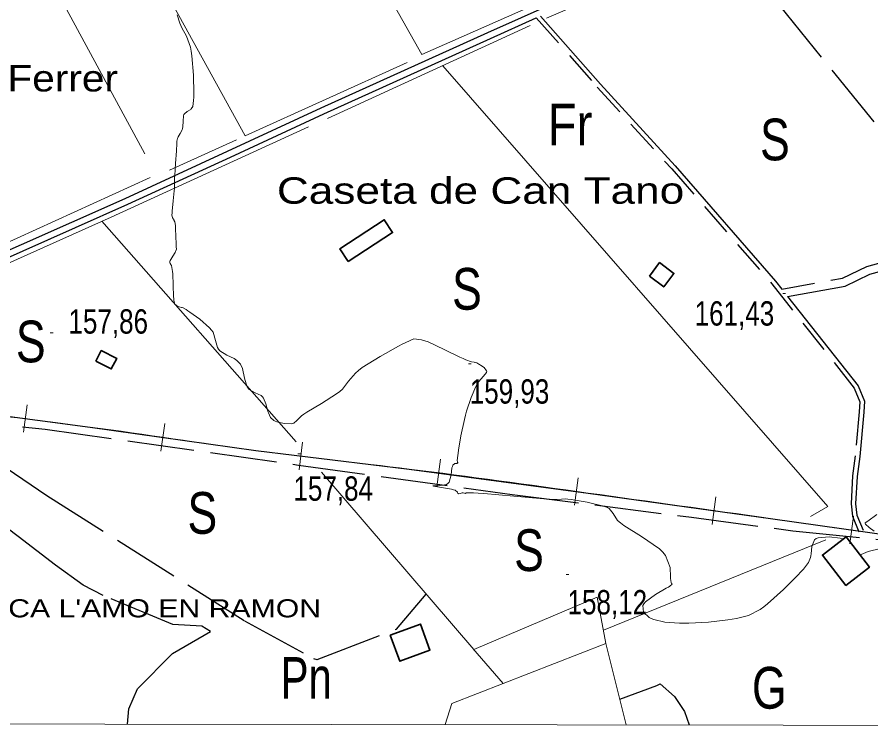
# Model space of a CAD drawing. Extents: x -807245 to 6129983, y -54972206 to 262146364.
# Drawn here: x 489594.4 to 489901.6, y 4381810.3 to 4382068.1 of the extents above; entities that cross this region are included whole.
import ezdxf
from ezdxf.enums import TextEntityAlignment as Align

# ---------------------------------------------------------------- set-up
doc = ezdxf.new("R2010")
doc.units = 0
doc.header["$LTSCALE"] = 4
doc.linetypes.add('LONG_DASHED', pattern=[7.5, 6, -1.5])
doc.linetypes.add('MEDIUM_DASHED', pattern=[4.5, 3, -1.5])
for name, color, linetype, lineweight in [('1', 7, 'Continuous', 13), ('25', 7, 'LONG_DASHED', 25), ('27', 7, 'Continuous', 25), ('38', 7, 'Continuous', 25), ('39', 7, 'Continuous', 13), ('47', 7, 'Continuous', 35), ('51', 7, 'Continuous', 13), ('7', 7, 'Continuous', 13), ('9', 7, 'Continuous', 13)]:
    doc.layers.add(name, color=color, linetype=linetype, lineweight=lineweight)
doc.layers.add('31', color=7, linetype='Continuous')
doc.layers.add('5', color=7, linetype='Continuous')

msp = doc.modelspace()

# ---------------------------------------------------------------- linework, layer by layer
at = {"layer": '1'}
msp.add_lwpolyline([(487678, 4384129), (491255.4, 4384123.8), (491252.6, 4381811.5), (487674.1, 4381816.7)], close=True, dxfattribs=at)
at = {"layer": '25'}
msp.add_line((489849.71, 4382095.68), (489987.15, 4381926.15), dxfattribs=at)
for points in [[(489452.44, 4381947.99), (489470.81, 4381945.01), (489504.4, 4381935.18), (489529.88, 4381929.13), (489553.54, 4381927.48), (489566.45, 4381923.64), (489604.56, 4381919.97), (489695.66, 4381907.04), (489772.54, 4381896.5), (489837.07, 4381888.24), (489873.55, 4381883.42), (489910.23, 4381879.72), (489957.75, 4381870.56), (490032.95, 4381858.19), (490087.19, 4381850.38), (490148.03, 4381842.93), (490197.43, 4381837.42), (490224.83, 4381836.07), (490255.25, 4381830.66), (490293.96, 4381826.86), (490348.9, 4381821.39)], [(489562.89, 4381924.71), (489605.15, 4381896.06), (489676.26, 4381851.04), (489701.09, 4381837.41), (489702.29, 4381837.14), (489702.37, 4381837.14), (489730.93, 4381848.04), (489741.63, 4381860.58)], [(489634.15, 4381813.85), (489634.66, 4381819.38), (489637.73, 4381826.5), (489650.35, 4381839.23), (489664.05, 4381847.18), (489660.86, 4381849.06), (489650.49, 4381849.73), (489625.44, 4381860.13), (489618.16, 4381863.87), (489608.25, 4381871), (489594.75, 4381881.28), (489586.21, 4381887.77), (489577.73, 4381895.08), (489567.94, 4381903.57), (489558.12, 4381913.63), (489556.12, 4381915.83), (489553.84, 4381913.16)], [(489811.23, 4381822.88), (489824.6, 4381827.75), (489825.78, 4381828.37), (489830.91, 4381823.83), (489834.55, 4381818.44), (489836.17, 4381813.56)]]:
    msp.add_lwpolyline(points, dxfattribs=at)
at = {"layer": '27'}
msp.add_spline([(491255.21, 4383970.03), (491244.34, 4383967.52), (491230.36, 4383957.66), (491230.81, 4383957.81), (491230.81, 4383957.81), (491220.15, 4383951.47), (491212.7, 4383943.01), (491205.06, 4383944.23), (491184.85, 4383957.71), (491152.82, 4383981.27), (491128.36, 4384004.58), (491128.29, 4384004.88), (491122.26, 4384021.39), (491095.75, 4384034.59), (491071.07, 4384059.32), (491064.71, 4384065.12)], degree=3, dxfattribs=at)
at = {"layer": '38'}
for points in [[(489532.56, 4381957.48), (489536.05, 4381958.89), (489576.74, 4381977.86), (489633.34, 4382002.95), (489670.16, 4382019.88), (489703.8, 4382035.47), (489763.73, 4382062.58), (489825.37, 4382090.18), (489886.58, 4382117.1), (489924.2, 4382133.95)], [(489150.21, 4381973.7), (489186.43, 4381969.89), (489217.49, 4381967.49), (489238.54, 4381965.85), (489269.93, 4381963.84), (489311.11, 4381960.54), (489355.93, 4381958), (489398.29, 4381954.28), (489439.39, 4381951.35), (489451.4, 4381951.23), (489463.3, 4381952.62), (489475.12, 4381953.31), (489487.87, 4381948.91), (489502.27, 4381945.57), (489507.66, 4381944.82), (489536.99, 4381956.73), (489577.71, 4381975.72), (489634.31, 4382000.8), (489671.15, 4382017.74), (489704.78, 4382033.33), (489764.7, 4382060.43), (489781.21, 4382067.82)], [(489782.76, 4382068.51), (489804.33, 4382044.05), (489831.15, 4382014.63), (489867.23, 4381973.2), (489869.5, 4381970.33)], [(489871.62, 4381967.65), (489892.31, 4381971.39), (489901.14, 4381975.63), (489912.92, 4381978.89), (489918.65, 4381980.97)], [(489871.62, 4381967.65), (489897.01, 4381935.53), (489899.3, 4381930.03), (489899.02, 4381926.05), (489897.56, 4381910.12), (489896.6, 4381902.97), (489896.06, 4381893.14), (489896.53, 4381889.02), (489898.75, 4381883.59)]]:
    msp.add_lwpolyline(points, dxfattribs=at)
at = {"layer": '38', "linetype": 'MEDIUM_DASHED'}
for points in [[(489781.21, 4382067.82), (489803.13, 4382042.97), (489829.95, 4382013.56), (489865.99, 4381972.17), (489895.61, 4381934.7), (489897.66, 4381929.76), (489897.41, 4381926.18), (489895.96, 4381910.3), (489894.99, 4381903.12), (489894.44, 4381893.09), (489894.95, 4381888.62), (489897.26, 4381882.98)], [(489869.5, 4381970.33), (489891.37, 4381974.29), (489900.07, 4381978.47), (489912, 4381981.77), (489917.62, 4381983.81)]]:
    msp.add_lwpolyline(points, dxfattribs=at)
at = {"layer": '39'}
for p, q in [((489596.7, 4381918.83), (489598.01, 4381928.74)), ((489646.19, 4381912.04), (489647.59, 4381921.94)), ((489695.84, 4381905.35), (489697.04, 4381915.27)), ((489745.39, 4381899.21), (489746.72, 4381909.12)), ((489794.95, 4381892.57), (489796.28, 4381902.48)), ((489844.45, 4381885.69), (489845.83, 4381895.59)), ((489893.96, 4381878.75), (489895.35, 4381888.65))]:
    msp.add_line(p, q, dxfattribs=at)
at = {"layer": '39', "lineweight": 25}
msp.add_lwpolyline([(489563.73, 4381928.23), (489620.66, 4381920.7), (489680.32, 4381912.26), (489735.44, 4381905.59), (489799.91, 4381896.95), (489865.43, 4381887.81), (489926.74, 4381879.18), (489976.6, 4381873.08), (490039.39, 4381865.3), (490107.84, 4381856.38), (490175.25, 4381846.83), (490254.89, 4381836.5), (490348.33, 4381823.47), (490406.14, 4381813.57), (490409.59, 4381812.73)], dxfattribs=at)
at = {"layer": '39'}
msp.add_spline([(489117.55, 4382698.88), (489119.92, 4382672.68), (489122.01, 4382625.33), (489125.29, 4382585.13), (489126.65, 4382547.13), (489128.77, 4382508.18), (489130.39, 4382475.59), (489130.93, 4382447.55), (489133.21, 4382401.71), (489136.74, 4382363.61), (489144.72, 4382321.33), (489154.17, 4382280.07), (489166.23, 4382246.73), (489180.75, 4382210.53), (489205.22, 4382168.24), (489224.8, 4382133.94), (489257.72, 4382093.12), (489296.35, 4382054.96), (489327.82, 4382028.88), (489364.04, 4382002), (489408.28, 4381978.37), (489453.5, 4381958.06), (489487.73, 4381946.36), (489523.65, 4381936.12), (489563.73, 4381928.23), (489620.66, 4381920.7), (489680.32, 4381912.26), (489735.44, 4381905.59), (489799.91, 4381896.95), (489865.43, 4381887.81), (489926.74, 4381879.18), (489976.6, 4381873.08), (490039.39, 4381865.3), (490107.84, 4381856.38), (490175.25, 4381846.83), (490254.89, 4381836.5), (490348.33, 4381823.47), (490406.14, 4381813.57), (490409.06, 4381812.73)], degree=3, dxfattribs=at)
at = {"layer": '47'}
for points in [[(489713.56, 4381980.26), (489729.49, 4381990.66), (489726.5, 4381995.24), (489710.57, 4381984.84)], [(489821.9, 4381974.98), (489825.55, 4381979.83), (489830.72, 4381975.93), (489827.07, 4381971.08)], [(489622.77, 4381944.44), (489628.3, 4381941.59), (489630.25, 4381945.36), (489624.72, 4381948.21)], [(489892.65, 4381881.21), (489901.07, 4381870.27), (489892.58, 4381863.73), (489884.16, 4381874.67)], [(489728.65, 4381845.89), (489732.1, 4381836.46), (489742.95, 4381840.43), (489739.5, 4381849.86)]]:
    msp.add_lwpolyline(points, close=True, dxfattribs=at)
at = {"layer": '51'}
for p, q in [((489706.13, 4382031.69), (489779.05, 4382065.09)), ((489649.31, 4382013.12), (489673.3, 4382024)), ((489532.79, 4381960.55), (489642.25, 4382010.42)), ((489624.88, 4381994.74), (489694.8, 4381915.35)), ((489805.35, 4381847.67), (489885.32, 4381880.15)), ((489806.27, 4381842.87), (489813.53, 4381813.59)), ((489758.34, 4381841.11), (489769.34, 4381828.46))]:
    msp.add_line(p, q, dxfattribs=at)
for points in [[(489571.72, 4382215.49), (489541.78, 4382200.81), (489640.41, 4382019)], [(489666.94, 4382184.13), (489739.98, 4382054.63), (489883.34, 4382117.92)], [(489784.91, 4382067.77), (489850.59, 4382096.06), (489925.38, 4382129.72), (490013.08, 4382169.29)], [(489625.49, 4382117.97), (489676.49, 4382025.49), (489734.71, 4382051.82)], [(489747.55, 4382050.66), (489886.03, 4381892.17), (489879.89, 4381888.58)], [(489529.46, 4381951.92), (489628.23, 4381996.24), (489699.3, 4382028.62)], [(489748.44, 4381813.69), (489750.87, 4381821.26), (489806.27, 4381842.87), (489803.05, 4381859.52), (489758.69, 4381840.7), (489703.89, 4381904.52)]]:
    msp.add_lwpolyline(points, dxfattribs=at)
at = {"layer": '7'}
for p, q in [((489869.91, 4381968.7), (489870.91, 4381968.7)), ((489606.37, 4381954.6), (489607.37, 4381954.6)), ((489756.76, 4381943.49), (489757.76, 4381943.49)), ((489695.37, 4381911.02), (489696.37, 4381911.02)), ((489791.95, 4381867.69), (489792.95, 4381867.69))]:
    msp.add_line(p, q, dxfattribs=at)
at = {"layer": '9'}
for points in [[(489651.36, 4381993.18), (489651.12, 4381994.46), (489650.83, 4381995.15), (489650.75, 4381995.32), (489650.66, 4381995.47), (489650.33, 4381995.9), (489650.15, 4381997.05), (489650.16, 4381997.65), (489650.2, 4381998.38), (489650.55, 4382002.02), (489650.95, 4382005.67), (489651.02, 4382006.4), (489651.07, 4382007.01), (489651.08, 4382008.19), (489651.07, 4382009.55), (489651.1, 4382010.28), (489651.14, 4382011.15), (489651.44, 4382015.54), (489651.76, 4382020.03), (489651.81, 4382020.96), (489651.86, 4382021.76), (489651.92, 4382023.53), (489652.08, 4382024.48), (489652.19, 4382024.77), (489652.33, 4382025.06), (489653.05, 4382026.22), (489653.76, 4382027.64), (489653.89, 4382028.11), (489653.99, 4382028.62), (489654.12, 4382030.7), (489654.3, 4382032.64), (489654.44, 4382033.05), (489654.62, 4382033.4), (489655.58, 4382034.23), (489656.64, 4382034.77), (489656.88, 4382034.95), (489657.09, 4382035.14), (489657.65, 4382035.93), (489657.93, 4382038.19), (489657.96, 4382039.31), (489657.98, 4382040.64), (489657.87, 4382047.22), (489657.34, 4382054.23), (489657.09, 4382055.83), (489656.79, 4382057.28), (489655.31, 4382061.31), (489653.73, 4382064.33), (489653.36, 4382065.16), (489653.02, 4382065.98), (489652.05, 4382068.9)], [(489758.84, 4381944.01), (489757.94, 4381944.12), (489755.82, 4381944.87), (489754.84, 4381945.3), (489753.68, 4381945.84), (489748.08, 4381948.62), (489742.32, 4381951.29), (489741.07, 4381951.76), (489739.96, 4381952.11), (489737.19, 4381952.4), (489734.23, 4381951.16), (489733.01, 4381950.54), (489731.6, 4381949.8), (489725.05, 4381946.13), (489718.62, 4381942.06), (489717.29, 4381941.06), (489716.16, 4381940.12), (489713.69, 4381937.17), (489711.47, 4381934.38), (489710.49, 4381933.54), (489709.36, 4381932.66), (489703.93, 4381929.21), (489698.63, 4381926.04), (489697.58, 4381925.33), (489696.7, 4381924.7), (489695.01, 4381923.02), (489693.98, 4381922.13), (489693.53, 4381921.99), (489693, 4381921.9), (489690.45, 4381921.97), (489687.85, 4381922.55), (489687.29, 4381922.77), (489686.79, 4381923.03), (489685.56, 4381924.19), (489684.83, 4381925.76), (489684.65, 4381926.27), (489684.47, 4381926.81), (489683.93, 4381929.03), (489683.05, 4381931.12), (489682.66, 4381931.58), (489682.21, 4381931.99), (489680.08, 4381933.02), (489677.96, 4381934.17), (489677.51, 4381934.66), (489677.14, 4381935.21), (489676.3, 4381937.82), (489675.81, 4381940.54), (489675.65, 4381941.17), (489675.47, 4381941.74), (489674.76, 4381943.35), (489673.53, 4381944.61), (489673.04, 4381944.96), (489672.47, 4381945.3), (489669.84, 4381946.56), (489667.36, 4381948.13), (489666.88, 4381948.68), (489666.49, 4381949.28), (489665.84, 4381951.84), (489664.93, 4381954.77), (489664.38, 4381955.6), (489663.7, 4381956.43), (489660.16, 4381959.52), (489656.58, 4381962.06), (489655.87, 4381962.54), (489655.29, 4381962.94), (489654.22, 4381963.57), (489653.83, 4381963.65), (489653.68, 4381963.69), (489653.51, 4381963.74), (489652.74, 4381963.98), (489651.96, 4381964.29), (489651.78, 4381964.39), (489651.61, 4381964.49), (489651.15, 4381964.87), (489650.84, 4381966.17), (489650.77, 4381966.85), (489650.71, 4381967.66), (489650.55, 4381971.72), (489650.39, 4381975.81), (489650.33, 4381976.64), (489650.27, 4381977.34), (489649.97, 4381978.75), (489649.67, 4381979.25), (489649.6, 4381979.37), (489649.53, 4381979.49), (489649.35, 4381979.85), (489649.43, 4381980.4), (489649.54, 4381980.64), (489649.68, 4381980.91), (489650.49, 4381982.21), (489651.31, 4381983.52), (489651.46, 4381983.8), (489651.58, 4381984.04), (489651.74, 4381984.63), (489651.67, 4381985.55), (489651.65, 4381986.01), (489651.63, 4381986.56), (489651.57, 4381989.26), (489651.45, 4381992.06), (489651.41, 4381992.66), (489651.36, 4381993.18)], [(489821.79, 4381852.26), (489819.73, 4381854.17), (489819.53, 4381856.49), (489819.91, 4381857.17), (489820.47, 4381857.87), (489824.1, 4381860.51), (489827.98, 4381862.74), (489828.71, 4381863.17), (489829.29, 4381863.53), (489830.12, 4381864.18), (489829.97, 4381864.34), (489829.92, 4381864.39), (489829.88, 4381864.44), (489829.71, 4381864.63), (489829.55, 4381865.62), (489829.51, 4381866.16), (489829.47, 4381866.83), (489829.37, 4381870.22), (489827.74, 4381874.45), (489826.74, 4381875.65), (489825.51, 4381876.86), (489819.09, 4381881.3), (489812.69, 4381885.32), (489811.46, 4381886.25), (489810.47, 4381887.11), (489808.88, 4381889.57), (489807.42, 4381891.39), (489806.52, 4381891.84), (489805.4, 4381892.27), (489799.55, 4381893.66), (489793.7, 4381894.59), (489792.59, 4381894.73), (489791.69, 4381894.83), (489790.28, 4381894.77), (489787.65, 4381894.7), (489786, 4381894.79), (489783.93, 4381894.93), (489773.13, 4381895.84), (489762.32, 4381896.77), (489760.26, 4381896.93), (489758.6, 4381897.04), (489755.97, 4381897.05), (489755.89, 4381896.87), (489755.83, 4381896.85), (489755.76, 4381896.84), (489755.4, 4381896.93), (489754.88, 4381897.02), (489754.72, 4381897.02), (489754.55, 4381897), (489753.85, 4381896.82), (489753.24, 4381896.74), (489753.12, 4381896.78), (489753.03, 4381896.85), (489752.87, 4381897.34), (489751.97, 4381898), (489751.42, 4381898.18), (489750.73, 4381898.36), (489747.11, 4381898.99), (489744.2, 4381899.46), (489743.96, 4381899.54), (489743.95, 4381899.59), (489745.96, 4381899.58), (489748.86, 4381900.07), (489749.42, 4381900.45), (489749.87, 4381900.92), (489750.64, 4381903.47), (489750.88, 4381906.06), (489751.01, 4381906.55), (489751.16, 4381906.95), (489751.9, 4381907.61), (489752.62, 4381907.65), (489752.75, 4381907.67), (489752.85, 4381907.69), (489752.99, 4381907.77), (489752.92, 4381907.97), (489752.9, 4381908.06), (489752.88, 4381908.16), (489752.78, 4381908.69), (489752.92, 4381910.42), (489753.04, 4381911.29), (489753.2, 4381912.33), (489754.1, 4381917.51), (489755.35, 4381923.45), (489755.73, 4381924.97), (489756.13, 4381926.45), (489757.72, 4381931.34), (489759.44, 4381935.27), (489759.92, 4381936.14), (489760.41, 4381936.92), (489762.17, 4381938.95), (489763.29, 4381940.29), (489763.37, 4381940.64), (489763.35, 4381940.97), (489762.44, 4381942.11), (489761.09, 4381943.01), (489760.79, 4381943.2), (489760.53, 4381943.36), (489759.83, 4381943.74), (489759.25, 4381943.92), (489759.06, 4381943.97), (489758.84, 4381944.01)], [(489903.68, 4381889.21), (489900.51, 4381886.84), (489899.51, 4381886.31), (489899.5, 4381886.08), (489899.6, 4381885.82), (489900.91, 4381884.57), (489902.8, 4381883.28)], [(489891.62, 4381880.41), (489891.31, 4381880.51), (489890.53, 4381880.7), (489886.56, 4381881.19), (489882.64, 4381880.88), (489881.89, 4381880.56), (489881.28, 4381880.15), (489880.28, 4381877.8), (489880.07, 4381875.09), (489879.96, 4381874.44), (489879.83, 4381873.84), (489879.16, 4381872.01), (489877.29, 4381869.58), (489876.39, 4381868.6), (489875.33, 4381867.47), (489870.16, 4381862.27), (489864.44, 4381857.13), (489863.04, 4381856.05), (489861.72, 4381855.11), (489857.6, 4381852.93), (489853.21, 4381851.83), (489851.71, 4381851.56), (489850.09, 4381851.32), (489843.21, 4381850.58), (489836.13, 4381850.2), (489834.38, 4381850.17), (489832.72, 4381850.19), (489827.49, 4381850.55), (489823.47, 4381851.47), (489822.58, 4381851.84), (489821.79, 4381852.26)], [(489905.04, 4381876.97), (489900.59, 4381875.98), (489898.04, 4381874.86), (489897.63, 4381874.74)]]:
    msp.add_lwpolyline(points, dxfattribs=at)

# ---------------------------------------------------------------- texts
at = {"layer": '31'}
for s, width, p in [('Fr', 0.85, (489793.34, 4382022.04)), ('S', 0.8, (489867.05, 4382016.62)), ('S', 0.8, (489756.26, 4381962.91)), ('S', 0.8, (489599.34, 4381943.97)), ('S', 0.8, (489661.07, 4381882.32)), ('S', 0.8, (489778.59, 4381868.92)), ('Pn', 0.75, (489698.45, 4381822.98)), ('G', 0.8, (489865.02, 4381819.43))]:
    msp.add_text(s, height=15, dxfattribs=dict(at, width=width)).set_placement(p, align=Align.CENTER)
at = {"layer": '5'}
for s, height, width, p in [("Casetes de n'Esteve Ferrer", 9.5, 1.15, (489453.34, 4382041.39)), ('Caseta de Can Tano', 9.5, 1.25, (489687.89, 4382001.01)), ("PLETA DE CA L'AMO EN RAMON", 6.5, 1.25, (489535.68, 4381852.26))]:
    msp.add_text(s, height=height, dxfattribs=dict(at, width=width)).set_placement(p)
at = {"layer": '7', "width": 0.8}
for s, p in [('161,43', (489838.17, 4381957.19)), ('157,86', (489612.9, 4381954.3)), ('159,93', (489757.26, 4381929.12)), ('157,84', (489693.83, 4381894.2)), ('158,12', (489792.45, 4381853.32))]:
    msp.add_text(s, height=8.75, dxfattribs=at).set_placement(p)

doc.saveas('drawing.dxf')
